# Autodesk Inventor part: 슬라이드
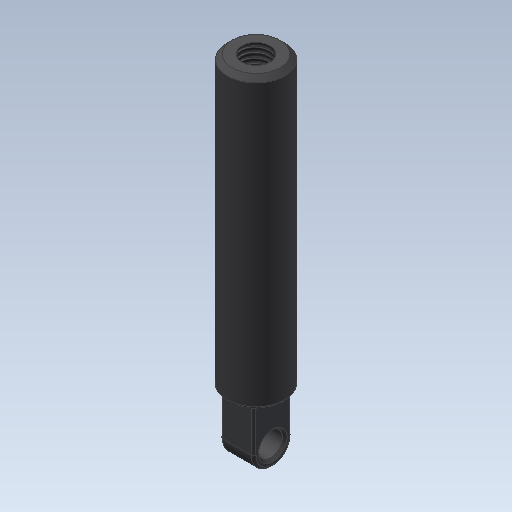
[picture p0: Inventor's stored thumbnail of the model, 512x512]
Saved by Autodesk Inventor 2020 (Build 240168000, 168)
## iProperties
Created: 2016-02
Part Number: 슬라이드
Material: 강철, 연강
Document SubType Name: Modeling
Designer: test
Density: 1 g/cm^3
Appearance: 회색
Author: test
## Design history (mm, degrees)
sketch "스케치2"
  geometry: C1 r 6 at (0, 0); 1 further point
  constraints: 1 centre point, 1 coincident
  dimensions: "d0" = 12 diameter of C1
extrude "돌출1" new body sketch "스케치2" distance "d1" = 60; taper "d2" = 0 deg
hole "구멍1" diameter "d5" = 5.917; stored, may be unused: countersink angle "d9" = 90 deg, drill point angle "d11" = 118 deg; dims "d3" = 10, "d4" = 10, "d6" = 10, "d7" = 4, "d8" = 2, "d10" = 12
chamfer "모따기1" distance "d12" = 1; stored, may be unused: second distance "d13" = 2, angle "d14" = 45 deg
sketch "스케치3"
  geometry: L1 (0, 6)-(0, -6) reference; L2 (0, 4)-(-9, 4); L3 (-9, -4)-(0, -4); L4 (0, -4)-(0, 4); C1 r 2.5 at (-9, 0); A1 r 4 centre (-9, 0) between (-9, 4) and (-9, -4); 2 further points
  constraints: 6 end point, 2 centre point, 2 point on circle, 2 tangent, 1 coincident, 1 horizontal, 1 horizontal alignment, 1 midpoint, 1 parallel, 1 point on line, 1 vertical
  dimensions: "d15" = 13 dimension on A1 L1; "d16" = 8 distance between parallel lines of L3 L2; "d17" = 5 diameter of C1
extrude "돌출2" join sketch "스케치3" stored distance "d18" = 7; taper "d19" = 0 deg
chamfer "모따기2" distance "d20" = 0.5; stored, may be unused: second distance "d21" = 2, angle "d22" = 45 deg
fillet "모깎기1" dims "d23" = 0.5
fillet "모깎기2" dims "d24" = 0.5
fillet "모깎기3" dims "d25" = 0.5
node "솔리드1"
